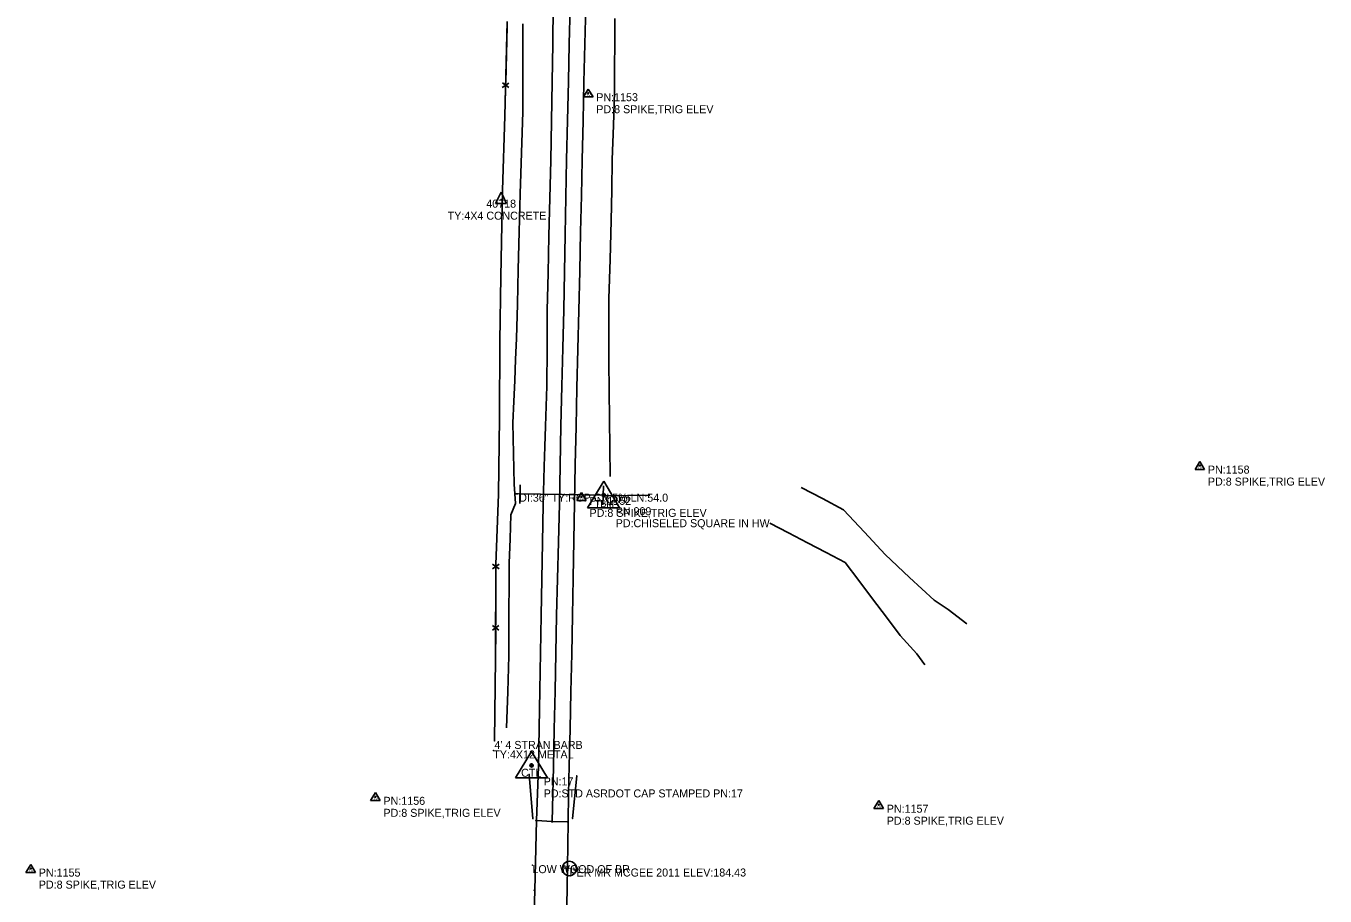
# Model space of a CAD drawing. Extents: x 1445297 to 1476720, y 2042269 to 2057889.
# Drawn here: x 1475909 to 1476720, y 2055423 to 2055966 of the extents above; entities that cross this region are included whole.
import ezdxf

# ---------------------------------------------------------------- set-up
doc = ezdxf.new("R2010")
doc.units = 0
for name, color, linetype in [('S_BRIDGE', 7, 'Continuous'), ('S_CROSS_DRAIN', 7, 'Continuous'), ('S_CROSS_DRAIN_ANNOT', 7, 'Continuous'), ('S_DITCHLINE', 7, 'Continuous'), ('S_DRG_PT_SYM', 7, 'Continuous'), ('S_EDGE_PAVEMENT', 7, 'Continuous'), ('S_EXIST_ROW', 7, 'Continuous'), ('S_EXIST_ROW_ANNOT', 7, 'Continuous'), ('S_FENCE', 7, 'Continuous'), ('S_FENCE_ANNOT', 7, 'Continuous'), ('S_GATE_ANNOT', 7, 'Continuous'), ('S_GUARDRAIL', 7, 'Continuous'), ('S_HEADWALL', 7, 'Continuous'), ('S_HIST_HIGH_WATER', 7, 'Continuous'), ('S_HIST_HIGH_WATER_ANNOT', 7, 'Continuous'), ('S_MSC_PT_SYM', 7, 'Continuous'), ('S_PAVEMENT_CROWN', 7, 'Continuous'), ('S_PRIMARY_CTL', 7, 'Continuous'), ('S_PRIMARY_CTL_ANNOT', 7, 'Continuous'), ('S_RDW_PT_SYM', 7, 'Continuous'), ('S_SECONDARY_CTL', 7, 'Continuous'), ('S_SECONDARY_CTL_ANNOT', 7, 'Continuous'), ('S_STR_PT_SYM', 7, 'Continuous'), ('S_SURVEY_TEXT_ANNOT', 7, 'Continuous')]:
    doc.layers.add(name, color=color, linetype=linetype)

msp = doc.modelspace()

# ---------------------------------------------------------------- linework, layer by layer
at = {"layer": 'S_BRIDGE'}
for p, q in [((1476226.59, 2055426.32), (1476227.61, 2055469.87)), ((1476227.61, 2055469.87), (1476237.45, 2055469.34)), ((1476237.45, 2055469.34), (1476247.41, 2055469.07)), ((1476247.41, 2055469.07), (1476247.02, 2055440.81)), ((1476247.02, 2055440.81), (1476246.16, 2055395.44)), ((1476225.79, 2055397.26), (1476226.59, 2055426.32))]:
    msp.add_line(p, q, dxfattribs=at)
at = {"layer": 'S_CROSS_DRAIN'}
msp.add_line((1476216.86, 2055674.15), (1476270.67, 2055673.24), dxfattribs=at)
at = {"layer": 'S_DITCHLINE'}
for points in [[(1476209.04, 2055527.77), (1476209.67, 2055550.34), (1476210.3, 2055572.92), (1476210.39, 2055587.37), (1476210.49, 2055601.83), (1476210.58, 2055616.28), (1476210.68, 2055630.73), (1476211.21, 2055645.87), (1476211.74, 2055661), (1476214.64, 2055668.01), (1476214.1, 2055674.09), (1476213.68, 2055680.08), (1476213.3, 2055699.29), (1476212.91, 2055718.49), (1476213.49, 2055731.66), (1476214.07, 2055744.83), (1476214.65, 2055758), (1476215.22, 2055771.17), (1476215.75, 2055792.65), (1476216.27, 2055814.14), (1476216.86, 2055837.82), (1476217.46, 2055861.49), (1476217.89, 2055874.3), (1476218.31, 2055887.1), (1476218.74, 2055899.9), (1476219.16, 2055912.7), (1476219.17, 2055926.49), (1476219.18, 2055940.27), (1476219.19, 2055954.05), (1476219.2, 2055967.83)], [(1476273.63, 2055684.87), (1476273.44, 2055702.76), (1476273.25, 2055720.65), (1476273.06, 2055738.54), (1476272.87, 2055756.44), (1476272.85, 2055776.25), (1476272.83, 2055796.07), (1476273.61, 2055820.42), (1476274.38, 2055844.77), (1476274.66, 2055863.89), (1476274.95, 2055883.01), (1476275.69, 2055904.14), (1476276.44, 2055925.27), (1476276.51, 2055940.52), (1476276.58, 2055955.76), (1476276.64, 2055971.01)], [(1476214.1, 2055674.09), (1476216.18, 2055674.06)], [(1476270.46, 2055672.74), (1476284.52, 2055672.97), (1476298.58, 2055673.19)], [(1476496.47, 2055592.85), (1476484.82, 2055601.72), (1476476.09, 2055607.55), (1476460.81, 2055621.83), (1476445.53, 2055636.11), (1476432.54, 2055650.1), (1476419.54, 2055664.09), (1476406.26, 2055671.07), (1476392.98, 2055678.04)], [(1476373.35, 2055655.71), (1476385.13, 2055649.6), (1476396.9, 2055643.48), (1476408.68, 2055637.36), (1476420.46, 2055631.25), (1476429.06, 2055619.83), (1476437.65, 2055608.41), (1476446.25, 2055596.98), (1476454.84, 2055585.56), (1476465.29, 2055574.1), (1476470.3, 2055567.12)]]:
    msp.add_lwpolyline(points, dxfattribs=at)
at = {"layer": 'S_DRG_PT_SYM'}
for points in [[(1476216.86, 2055674.15), (1476216.86, 2055674.2), (1476216.86, 2055674.15), (1476216.81, 2055674.15), (1476216.86, 2055674.15), (1476216.86, 2055674.1), (1476216.86, 2055674.15), (1476216.91, 2055674.15)], [(1476270.67, 2055673.24), (1476270.67, 2055673.29), (1476270.67, 2055673.24), (1476270.62, 2055673.24), (1476270.67, 2055673.24), (1476270.67, 2055673.19), (1476270.67, 2055673.24), (1476270.72, 2055673.24)]]:
    msp.add_lwpolyline(points, dxfattribs=at)
at = {"layer": 'S_EDGE_PAVEMENT'}
for points in [[(1476227.61, 2055469.87), (1476228.23, 2055486.78), (1476228.85, 2055503.7), (1476229.29, 2055527.59), (1476229.72, 2055551.48), (1476230.16, 2055574.73), (1476230.61, 2055597.98), (1476230.97, 2055620.82), (1476231.34, 2055643.66), (1476231.86, 2055667.42), (1476232.38, 2055691.18), (1476232.83, 2055703.72), (1476233.27, 2055716.25), (1476233.72, 2055728.79), (1476234.17, 2055741.33), (1476234.3, 2055765.03), (1476234.43, 2055788.73), (1476234.95, 2055811.96), (1476235.47, 2055835.18), (1476236.02, 2055858.77), (1476236.57, 2055882.35), (1476237.05, 2055906.94), (1476237.54, 2055931.54), (1476237.8, 2055955.33), (1476238.05, 2055979.13)], [(1476247.41, 2055469.07), (1476247.72, 2055486.59), (1476248.03, 2055504.1), (1476248.63, 2055527.2), (1476249.23, 2055550.3), (1476249.66, 2055574.14), (1476250.09, 2055597.98), (1476250.51, 2055621.41), (1476250.93, 2055644.84), (1476251.39, 2055668.48), (1476251.84, 2055692.11), (1476252.38, 2055716.19), (1476252.92, 2055740.28), (1476253.52, 2055764.42), (1476254.12, 2055788.56), (1476254.69, 2055813.16), (1476255.26, 2055837.77), (1476255.75, 2055860.29), (1476256.23, 2055882.82), (1476256.78, 2055907.07), (1476257.33, 2055931.32), (1476257.96, 2055955), (1476258.58, 2055978.68)]]:
    msp.add_lwpolyline(points, dxfattribs=at)
at = {"layer": 'S_EXIST_ROW'}
for p, q in [((1476205.51, 2055862.58), (1476201.98, 2055855.49)), ((1476205.51, 2055862.58), (1476209, 2055855.49)), ((1476201.98, 2055855.49), (1476209, 2055855.49)), ((1476205.5, 2055857.86), (1476205.5, 2055857.86))]:
    msp.add_line(p, q, dxfattribs=at)
for radius in [0.12, 0.06]:
    msp.add_circle((1476205.5, 2055857.86), radius, dxfattribs=at)
at = {"layer": 'S_FENCE'}
for p, q in [((1476207.86, 2055910.06), (1476209.45, 2055969.27)), ((1476206.29, 2055928), (1476210.46, 2055930.76)), ((1476210.39, 2055927.89), (1476206.37, 2055930.87)), ((1476206.53, 2055863.75), (1476207.86, 2055910.06)), ((1476205.49, 2055809.95), (1476206.53, 2055863.75)), ((1476204.81, 2055769.48), (1476205.49, 2055809.95)), ((1476204.49, 2055721.55), (1476204.81, 2055769.48)), ((1476203.9, 2055673.88), (1476204.49, 2055721.55)), ((1476202.23, 2055629.89), (1476203.9, 2055673.88)), ((1476204.27, 2055627.21), (1476200.18, 2055630.08)), ((1476200.18, 2055627.21), (1476204.28, 2055630.08)), ((1476202.17, 2055571.27), (1476202.23, 2055629.89)), ((1476204.23, 2055588.96), (1476200.14, 2055591.83)), ((1476200.14, 2055588.97), (1476204.24, 2055591.83)), ((1476201.4, 2055519.67), (1476202.17, 2055571.27))]:
    msp.add_line(p, q, dxfattribs=at)
for points in [[(1476208.43, 2055931.13), (1476209.37, 2055966.26)], [(1476207.86, 2055910.06), (1476208.33, 2055927.62)], [(1476206.53, 2055863.75), (1476207.86, 2055910.06)], [(1476205.49, 2055809.95), (1476206.53, 2055863.75)], [(1476204.81, 2055769.48), (1476205.49, 2055809.95)], [(1476204.49, 2055721.55), (1476204.81, 2055769.48)], [(1476203.9, 2055673.88), (1476204.49, 2055721.55)], [(1476202.23, 2055629.89), (1476203.9, 2055673.88)], [(1476202.19, 2055592.14), (1476202.23, 2055626.91)], [(1476202.17, 2055571.27), (1476202.18, 2055588.66)], [(1476201.4, 2055519.67), (1476202.17, 2055571.27)]]:
    msp.add_lwpolyline(points, dxfattribs=at)
at = {"layer": 'S_GUARDRAIL'}
for p, q in [((1476223.14, 2055498.75), (1476225.49, 2055471.06)), ((1476250.2, 2055471.21), (1476252.85, 2055497.9))]:
    msp.add_line(p, q, dxfattribs=at)
at = {"layer": 'S_HEADWALL'}
for points in [[(1476217.36, 2055667.98), (1476217.4, 2055679.74)], [(1476269.22, 2055667.17), (1476269.63, 2055679.01)]]:
    msp.add_lwpolyline(points, dxfattribs=at)
at = {"layer": 'S_HIST_HIGH_WATER'}
msp.add_circle((1476248.23, 2055439.95), 4.5, dxfattribs=at)
at = {"layer": 'S_MSC_PT_SYM'}
for points in [[(1476207.86, 2055910.06), (1476207.86, 2055910.11), (1476207.86, 2055910.06), (1476207.81, 2055910.06), (1476207.86, 2055910.06), (1476207.86, 2055910.01), (1476207.86, 2055910.06), (1476207.91, 2055910.06)], [(1476206.53, 2055863.75), (1476206.53, 2055863.8), (1476206.53, 2055863.75), (1476206.48, 2055863.75), (1476206.53, 2055863.75), (1476206.53, 2055863.7), (1476206.53, 2055863.75), (1476206.58, 2055863.75)], [(1476205.49, 2055809.95), (1476205.49, 2055810), (1476205.49, 2055809.95), (1476205.44, 2055809.95), (1476205.49, 2055809.95), (1476205.49, 2055809.9), (1476205.49, 2055809.95), (1476205.54, 2055809.95)], [(1476204.81, 2055769.48), (1476204.81, 2055769.53), (1476204.81, 2055769.48), (1476204.76, 2055769.48), (1476204.81, 2055769.48), (1476204.81, 2055769.43), (1476204.81, 2055769.48), (1476204.86, 2055769.48)], [(1476204.49, 2055721.55), (1476204.49, 2055721.6), (1476204.49, 2055721.55), (1476204.44, 2055721.55), (1476204.49, 2055721.55), (1476204.49, 2055721.5), (1476204.49, 2055721.55), (1476204.54, 2055721.55)], [(1476203.9, 2055673.88), (1476203.9, 2055673.93), (1476203.9, 2055673.88), (1476203.85, 2055673.88), (1476203.9, 2055673.88), (1476203.9, 2055673.83), (1476203.9, 2055673.88), (1476203.95, 2055673.88)], [(1476202.23, 2055629.89), (1476202.23, 2055629.94), (1476202.23, 2055629.89), (1476202.18, 2055629.89), (1476202.23, 2055629.89), (1476202.23, 2055629.84), (1476202.23, 2055629.89), (1476202.28, 2055629.89)], [(1476202.17, 2055571.27), (1476202.17, 2055571.32), (1476202.17, 2055571.27), (1476202.12, 2055571.27), (1476202.17, 2055571.27), (1476202.17, 2055571.22), (1476202.17, 2055571.27), (1476202.22, 2055571.27)], [(1476201.4, 2055519.67), (1476201.4, 2055519.72), (1476201.4, 2055519.67), (1476201.35, 2055519.67), (1476201.4, 2055519.67), (1476201.4, 2055519.62), (1476201.4, 2055519.67), (1476201.45, 2055519.67)], [(1476200.68, 2055513.71), (1476200.68, 2055513.76), (1476200.68, 2055513.71), (1476200.63, 2055513.71), (1476200.68, 2055513.71), (1476200.68, 2055513.66), (1476200.68, 2055513.71), (1476200.73, 2055513.71)], [(1476225.13, 2055442.04), (1476225.13, 2055442.09), (1476225.13, 2055442.04), (1476225.08, 2055442.04), (1476225.13, 2055442.04), (1476225.13, 2055441.99), (1476225.13, 2055442.04), (1476225.18, 2055442.04)]]:
    msp.add_lwpolyline(points, dxfattribs=at)
at = {"layer": 'S_PAVEMENT_CROWN'}
msp.add_lwpolyline([(1476237.45, 2055469.34), (1476237.91, 2055486.43), (1476238.37, 2055503.52), (1476238.82, 2055527.1), (1476239.28, 2055550.67), (1476239.76, 2055574.41), (1476240.24, 2055598.14), (1476240.86, 2055621.02), (1476241.47, 2055643.9), (1476241.95, 2055667.85), (1476242.42, 2055691.8), (1476242.95, 2055716.55), (1476243.47, 2055741.3), (1476244.15, 2055765.16), (1476244.84, 2055789.02), (1476245.22, 2055812.54), (1476245.6, 2055836.07), (1476246.01, 2055859.39), (1476246.43, 2055882.71), (1476247.05, 2055907.23), (1476247.67, 2055931.74), (1476248.15, 2055955.2), (1476248.64, 2055978.65)], dxfattribs=at)
at = {"layer": 'S_PRIMARY_CTL'}
for p, q in [((1476269.65, 2055681.91), (1476259.62, 2055665.39)), ((1476269.65, 2055681.91), (1476279.48, 2055665.39)), ((1476259.62, 2055665.39), (1476279.48, 2055665.39)), ((1476224.65, 2055513.07), (1476214.62, 2055496.55)), ((1476224.65, 2055513.07), (1476234.48, 2055496.55)), ((1476214.62, 2055496.55), (1476234.48, 2055496.55))]:
    msp.add_line(p, q, dxfattribs=at)
for centre, radius in [((1476269.65, 2055673.21), 1.04), ((1476269.65, 2055673.21), 0.609), ((1476269.65, 2055673.21), 0.344), ((1476224.65, 2055504.37), 1.04), ((1476224.65, 2055504.37), 0.609), ((1476224.65, 2055504.37), 0.344)]:
    msp.add_circle(centre, radius, dxfattribs=at)
at = {"layer": 'S_RDW_PT_SYM'}
for points in [[(1476223.14, 2055498.75), (1476223.14, 2055498.8), (1476223.14, 2055498.75), (1476223.09, 2055498.75), (1476223.14, 2055498.75), (1476223.14, 2055498.7), (1476223.14, 2055498.75), (1476223.19, 2055498.75)], [(1476252.85, 2055497.9), (1476252.85, 2055497.95), (1476252.85, 2055497.9), (1476252.8, 2055497.9), (1476252.85, 2055497.9), (1476252.85, 2055497.85), (1476252.85, 2055497.9), (1476252.9, 2055497.9)], [(1476225.49, 2055471.06), (1476225.49, 2055471.11), (1476225.49, 2055471.06), (1476225.44, 2055471.06), (1476225.49, 2055471.06), (1476225.49, 2055471.01), (1476225.49, 2055471.06), (1476225.54, 2055471.06)], [(1476250.2, 2055471.21), (1476250.2, 2055471.26), (1476250.2, 2055471.21), (1476250.15, 2055471.21), (1476250.2, 2055471.21), (1476250.2, 2055471.16), (1476250.2, 2055471.21), (1476250.25, 2055471.21)]]:
    msp.add_lwpolyline(points, dxfattribs=at)
at = {"layer": 'S_SECONDARY_CTL'}
for p, q in [((1476260.03, 2055927), (1476257.02, 2055922.05)), ((1476260.03, 2055927), (1476262.98, 2055922.05)), ((1476257.02, 2055922.05), (1476262.98, 2055922.05)), ((1476642.13, 2055694.32), (1476639.12, 2055689.36)), ((1476639.12, 2055689.36), (1476645.08, 2055689.36)), ((1476642.13, 2055694.32), (1476645.08, 2055689.36)), ((1476255.81, 2055674.79), (1476252.8, 2055669.83)), ((1476255.81, 2055674.79), (1476258.75, 2055669.83)), ((1476252.8, 2055669.83), (1476258.75, 2055669.83)), ((1476127.07, 2055487.35), (1476124.06, 2055482.4)), ((1476127.07, 2055487.35), (1476130.02, 2055482.4)), ((1476124.06, 2055482.4), (1476130.02, 2055482.4)), ((1476441.5, 2055482.42), (1476438.49, 2055477.47)), ((1476441.5, 2055482.42), (1476444.45, 2055477.47)), ((1476438.49, 2055477.47), (1476444.45, 2055477.47)), ((1475911.75, 2055442.49), (1475908.74, 2055437.54)), ((1475911.75, 2055442.49), (1475914.7, 2055437.54)), ((1475908.74, 2055437.54), (1475914.7, 2055437.54))]:
    msp.add_line(p, q, dxfattribs=at)
for centre, radius in [((1476260.03, 2055924.39), 0.311), ((1476260.03, 2055924.39), 0.183), ((1476260.03, 2055924.39), 0.103), ((1476642.13, 2055691.71), 0.311), ((1476642.13, 2055691.71), 0.183), ((1476642.13, 2055691.71), 0.103), ((1476255.81, 2055672.18), 0.311), ((1476255.81, 2055672.18), 0.183), ((1476255.81, 2055672.18), 0.103), ((1476127.07, 2055484.74), 0.311), ((1476127.07, 2055484.74), 0.183), ((1476127.07, 2055484.74), 0.103), ((1476441.5, 2055479.81), 0.311), ((1476441.5, 2055479.81), 0.183), ((1476441.5, 2055479.81), 0.103), ((1475911.75, 2055439.88), 0.311), ((1475911.75, 2055439.88), 0.183), ((1475911.75, 2055439.88), 0.103)]:
    msp.add_circle(centre, radius, dxfattribs=at)
at = {"layer": 'S_STR_PT_SYM'}
for points in [[(1476227.61, 2055469.87), (1476227.61, 2055470.37), (1476227.61, 2055469.87), (1476227.11, 2055469.87), (1476227.61, 2055469.87), (1476227.61, 2055469.37), (1476227.61, 2055469.87), (1476228.11, 2055469.87)], [(1476237.45, 2055469.34), (1476237.45, 2055469.84), (1476237.45, 2055469.34), (1476236.95, 2055469.34), (1476237.45, 2055469.34), (1476237.45, 2055468.84), (1476237.45, 2055469.34), (1476237.95, 2055469.34)], [(1476247.41, 2055469.07), (1476247.41, 2055469.57), (1476247.41, 2055469.07), (1476246.91, 2055469.07), (1476247.41, 2055469.07), (1476247.41, 2055468.57), (1476247.41, 2055469.07), (1476247.91, 2055469.07)], [(1476247.02, 2055440.81), (1476247.02, 2055441.31), (1476247.02, 2055440.81), (1476246.52, 2055440.81), (1476247.02, 2055440.81), (1476247.02, 2055440.31), (1476247.02, 2055440.81), (1476247.52, 2055440.81)], [(1476226.59, 2055426.32), (1476226.59, 2055426.82), (1476226.59, 2055426.32), (1476226.09, 2055426.32), (1476226.59, 2055426.32), (1476226.59, 2055425.82), (1476226.59, 2055426.32), (1476227.09, 2055426.32)]]:
    msp.add_lwpolyline(points, dxfattribs=at)

# ---------------------------------------------------------------- texts
at = {"layer": 'S_CROSS_DRAIN_ANNOT'}
for s, p in [('DI:36" TY:RCP CN:5% LN:54.0', (1476216.86, 2055669.15)), ('CN:0', (1476270.67, 2055668.24))]:
    msp.add_text(s, height=5, dxfattribs=at).set_placement(p)
at = {"layer": 'S_EXIST_ROW_ANNOT'}
for s, p in [('40718', (1476196.32, 2055852.86)), ('TY:4X4 CONCRETE', (1476172.19, 2055845.36))]:
    msp.add_text(s, height=5, dxfattribs=at).set_placement(p)
at = {"layer": 'S_FENCE_ANNOT'}
msp.add_text("4' 4 STRAN BARB", height=5, dxfattribs=at).set_placement((1476201.4, 2055514.67))
at = {"layer": 'S_GATE_ANNOT'}
msp.add_text('TY:4X12 METAL', height=5, dxfattribs=at).set_placement((1476200.68, 2055508.71))
at = {"layer": 'S_HIST_HIGH_WATER'}
msp.add_text('HHW', height=3, dxfattribs=at).set_placement((1476244.14, 2055438.45))
at = {"layer": 'S_HIST_HIGH_WATER_ANNOT'}
msp.add_text('PER MR MCGEE 2011 ELEV:184.43', height=5, dxfattribs=at).set_placement((1476248.23, 2055434.95))
at = {"layer": 'S_PRIMARY_CTL'}
for s, height, p in [('TBM', 4.287, (1476264, 2055665.82)), ('CTL', 5, (1476218.06, 2055497.29))]:
    msp.add_text(s, height=height, dxfattribs=at).set_placement(p)
at = {"layer": 'S_PRIMARY_CTL_ANNOT'}
for s, p in [('PN:909', (1476277.15, 2055660.71)), ('PD:CHISELED SQUARE IN HW', (1476277.15, 2055653.21)), ('PN:17', (1476232.15, 2055491.87)), ('PD:STD ASRDOT CAP STAMPED PN:17', (1476232.15, 2055484.37))]:
    msp.add_text(s, height=5, dxfattribs=at).set_placement(p)
at = {"layer": 'S_SECONDARY_CTL'}
for p in [(1476258.82, 2055922.38), (1476640.92, 2055689.7), (1476254.6, 2055670.17), (1476125.87, 2055482.73), (1476440.3, 2055477.8), (1475910.54, 2055437.87)]:
    msp.add_text('TV', height=1.5, dxfattribs=at).set_placement(p)
at = {"layer": 'S_SECONDARY_CTL_ANNOT'}
for s, p in [('PN:1153', (1476265.03, 2055919.39)), ('PD:8 SPIKE,TRIG ELEV', (1476265.03, 2055911.89)), ('PN:1158', (1476647.13, 2055686.71)), ('PD:8 SPIKE,TRIG ELEV', (1476647.13, 2055679.21)), ('PN:1152', (1476260.81, 2055667.18)), ('PD:8 SPIKE,TRIG ELEV', (1476260.81, 2055659.68)), ('PN:1156', (1476132.07, 2055479.74)), ('PN:1157', (1476446.5, 2055474.81)), ('PD:8 SPIKE,TRIG ELEV', (1476132.07, 2055472.24)), ('PD:8 SPIKE,TRIG ELEV', (1476446.5, 2055467.31)), ('PN:1155', (1475916.75, 2055434.88)), ('PD:8 SPIKE,TRIG ELEV', (1475916.75, 2055427.38))]:
    msp.add_text(s, height=5, dxfattribs=at).set_placement(p)
at = {"layer": 'S_SURVEY_TEXT_ANNOT'}
msp.add_text('LOW WOOD OF BR', height=5, dxfattribs=at).set_placement((1476225.13, 2055437.04))

doc.saveas('drawing.dxf')
